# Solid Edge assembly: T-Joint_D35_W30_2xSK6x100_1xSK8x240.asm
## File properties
Author: fknapp
Template: iso metric assembly.asm
Last saved by: fknapp
Revision: 7
Application: Solid Edge
Username: fknapp
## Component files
T-Joint_D35_W30.par
SK Knapp Schraube 8x240_ohne_Gewinde_22042020.par
SK Schraube 6x100_ohne_Gewinde.par
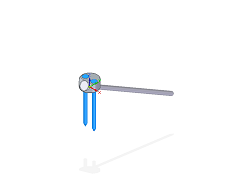
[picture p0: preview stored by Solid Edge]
